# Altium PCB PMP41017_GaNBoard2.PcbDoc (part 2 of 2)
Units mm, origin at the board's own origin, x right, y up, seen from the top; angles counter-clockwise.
Board outline 21.1 x 35.1 mm, 4 copper layers (Top Layer, Layer 1, Layer 2, Bottom Layer), stack 1.926 mm thick; 28 components, 38 nets, 164 pads, 603 vias.
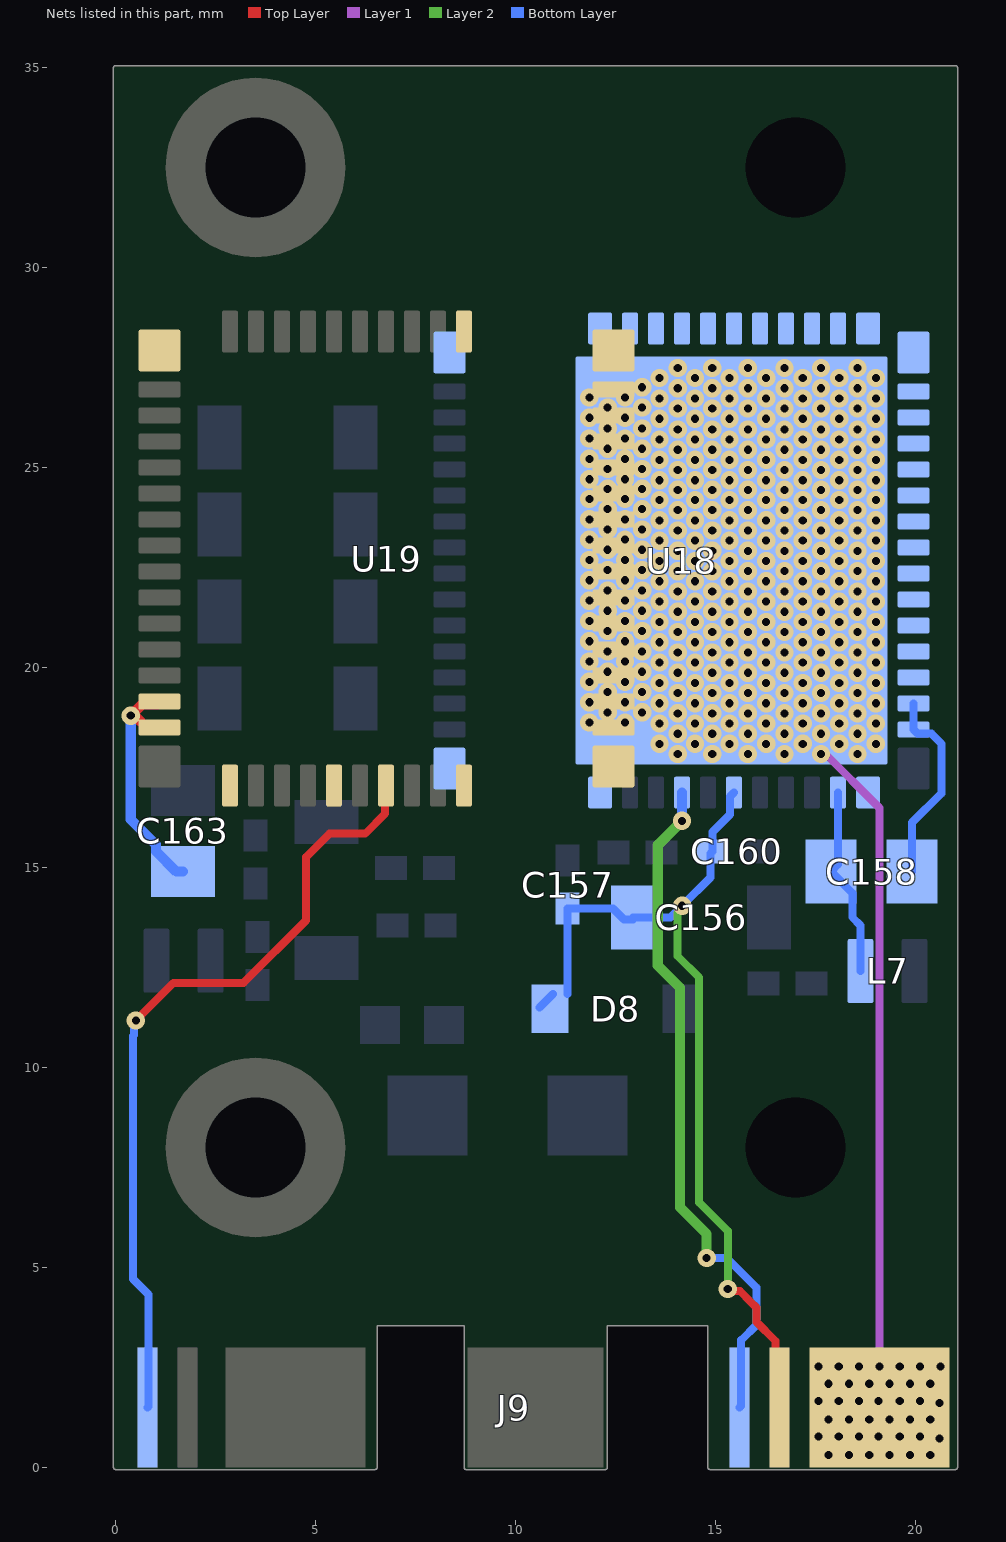
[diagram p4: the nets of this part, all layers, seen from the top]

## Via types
v1: diameter 0.457, hole 0.203, Top Layer to Bottom Layer, tented both sides, 603 vias

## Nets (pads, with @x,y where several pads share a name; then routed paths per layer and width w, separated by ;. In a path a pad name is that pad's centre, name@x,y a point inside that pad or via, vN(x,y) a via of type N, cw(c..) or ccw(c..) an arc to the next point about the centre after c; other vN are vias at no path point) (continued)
SW: C156.2 C157.2 C158.2 C160.1 D8.2 J9.8 J9.SW L7.1 U18.18 U18.19 U18.20 U18.21 U18.22 U18.23 U18.24 U18.25 U18.26 U18.27 U18.29 U18.30 U18.31 U18.32 U18.33 U18.34 U18.35 U18.36 U18.37 U18.38 U18.39 U18.40 U18.44 U18.45 U18.49 U18.55 U19.2 U19.3 U19.4 U19.5 U19.6 U19.7 U19.8 U19.9 U19.10 U19.11 U19.12 U19.13 U19.14 U19.15 | length 44.7
  Top Layer w0.2: v1(15.306,4.464) 15.354,4.417 15.606,4.417 15.877,4.146 16.023,4 16.023,3.641 16.495,3.169 16.495,1.605 J9.8@16.6,1.5
  Layer 1 w0.2: v1@17.694,17.894 19.1,16.488 J9.SW@19.1,1.5
  Layer 2 w0.2: v1(14.167,14.046) 14.167,13.976 14.056,13.865 14.056,12.784 14.592,12.248 14.592,6.628 15.306,5.914 v1(15.306,4.464)
  Bottom Layer w0.2: D8.2@10.601,11.5 D8.2@10.938,11.837 ; D8.2@11.3,11.837 C157.2@11.3,13.973 12.437,13.973 12.71,13.7 C156.2@12.94,13.7 ; C156.2@12.94,13.754 13.873,13.754 14.165,14.046 14.873,14.754 14.873,15.349 C160.1@14.929,15.405 14.927,15.407 14.927,15.888 15.365,16.326 15.365,16.775 U18.49@15.465,16.875 ; U18.45@18.065,16.875 18.065,15.081 C158.2@17.884,14.9 18.419,14.365 18.419,13.758 18.625,13.552 L7.1@18.625,12.411
  other v1: 17.828,0.315 18.336,0.315 18.844,0.315 19.352,0.315 19.86,0.315 20.368,0.315 20.597,0.722 17.574,0.772 18.082,0.772 18.59,0.772 19.073,0.772 19.606,0.772 20.114,0.772 17.828,1.204 18.336,1.204 18.844,1.204 19.352,1.204 19.86,1.204 20.368,1.204 20.597,1.611 17.574,1.661 18.082,1.661 18.59,1.661 19.073,1.661 19.606,1.661 20.114,1.661 17.828,2.093 18.336,2.093 18.844,2.093 19.352,2.093 19.86,2.093 20.368,2.093 17.574,2.525 18.082,2.525 18.59,2.525 19.098,2.525 19.606,2.525 20.114,2.525 20.622,2.525 14.056,17.837 14.919,17.837 15.808,17.837 16.723,17.837 17.637,17.837 18.552,17.837 13.599,18.091 14.488,18.091 15.351,18.091 16.266,18.091 17.18,18.091 18.094,18.091 19.009,18.091 14.056,18.345 14.919,18.345 15.808,18.345 16.723,18.345 17.637,18.345 18.552,18.345 13.599,18.599 14.488,18.599 15.351,18.599 16.266,18.599 17.18,18.599 18.094,18.599 19.009,18.599 11.846,18.625 12.735,18.625 14.056,18.853 14.919,18.853 15.808,18.853 16.723,18.853 17.637,18.853 18.552,18.853 12.303,18.879 13.167,18.879 13.599,19.107 14.488,19.107 15.351,19.107 16.266,19.107 17.18,19.107 18.094,19.107 19.009,19.107 11.846,19.133 12.735,19.133 14.056,19.361 14.919,19.361 15.808,19.361 16.723,19.361 17.637,19.361 18.552,19.361 12.303,19.387 13.167,19.387 13.599,19.615 14.488,19.615 15.351,19.615 16.266,19.615 17.18,19.615 18.094,19.615 19.009,19.615 11.846,19.641 12.735,19.641 14.056,19.869 14.919,19.869 15.808,19.869 16.723,19.869 17.637,19.869 18.552,19.869 12.303,19.895 13.167,19.895 13.599,20.123 14.488,20.123 15.351,20.123 16.266,20.123 17.18,20.123 18.094,20.123 19.009,20.123 11.846,20.149 12.735,20.149 14.056,20.377 14.919,20.377 15.808,20.377 16.723,20.377 17.637,20.377 18.552,20.377 12.303,20.403 13.167,20.403 13.599,20.631 14.488,20.631 15.351,20.631 16.266,20.631 17.18,20.631 18.094,20.631 19.009,20.631 11.846,20.657 12.735,20.657 14.056,20.885 14.919,20.885 15.808,20.885 16.723,20.885 17.637,20.885 18.552,20.885 12.303,20.911 13.167,20.911 13.599,21.139 14.488,21.139 15.351,21.139 16.266,21.139 17.18,21.139 18.094,21.139 19.009,21.139 11.846,21.165 12.735,21.165 14.056,21.393 14.919,21.393 15.808,21.393 16.723,21.393 17.637,21.393 18.552,21.393 12.303,21.419 13.167,21.419 13.599,21.647 14.488,21.647 15.351,21.647 16.266,21.647 17.18,21.647 18.094,21.647 19.009,21.647 11.846,21.673 12.735,21.673 14.056,21.901 14.919,21.901 15.808,21.901 16.723,21.901 17.637,21.901 18.552,21.901 12.303,21.927 13.167,21.927 13.599,22.155 14.488,22.155 15.351,22.155 16.266,22.155 17.18,22.155 18.094,22.155 19.009,22.155 11.846,22.181 12.735,22.181 14.056,22.409 14.919,22.409 15.808,22.409 16.723,22.409 17.637,22.409 18.552,22.409 12.303,22.435 13.167,22.435 13.599,22.663 14.488,22.663 15.351,22.663 16.266,22.663 17.18,22.663 18.094,22.663 19.009,22.663 11.846,22.689 12.735,22.689 14.056,22.917 14.919,22.917 15.808,22.917 16.723,22.917 17.637,22.917 18.552,22.917 12.303,22.943 13.167,22.943 13.599,23.171 14.488,23.171 15.351,23.171 16.266,23.171 17.18,23.171 18.094,23.171 19.009,23.171 11.846,23.197 12.735,23.197 14.056,23.425 14.919,23.425 15.808,23.425 16.723,23.425 17.637,23.425 18.552,23.425 12.303,23.451 13.167,23.451 13.599,23.679 14.488,23.679 15.351,23.679 16.266,23.679 17.18,23.679 18.094,23.679 19.009,23.679 11.846,23.705 12.735,23.705 14.056,23.933 14.919,23.933 15.808,23.933 16.723,23.933 17.637,23.933 18.552,23.933 12.303,23.959 13.167,23.959 13.599,24.187 14.488,24.187 15.351,24.187 16.266,24.187 17.18,24.187 18.094,24.187 19.009,24.187 11.846,24.213 12.735,24.213 14.056,24.441 14.919,24.441 15.808,24.441 16.723,24.441 17.637,24.441 18.552,24.441 12.303,24.467 13.167,24.467 13.599,24.683 14.488,24.683 15.351,24.683 16.266,24.683 17.18,24.683 18.094,24.683 19.009,24.683 11.846,24.708 12.735,24.708 14.056,24.937 14.919,24.937 15.808,24.937 16.723,24.937 17.637,24.937 18.552,24.937 12.303,24.962 13.167,24.962 13.599,25.191 14.488,25.191 15.351,25.191 16.266,25.191 17.18,25.191 18.094,25.191 19.009,25.191 11.846,25.216 12.735,25.216 14.056,25.445 14.919,25.445 15.808,25.445 16.723,25.445 17.637,25.445 18.552,25.445 12.303,25.47 13.167,25.47 13.599,25.699 14.488,25.699 15.351,25.699 16.266,25.699 17.18,25.699 18.094,25.699 19.009,25.699 11.846,25.724 12.735,25.724 14.056,25.953 14.919,25.953 15.808,25.953 16.723,25.953 17.637,25.953 18.552,25.953 12.303,25.978 13.167,25.978 13.599,26.219 14.488,26.219 15.351,26.219 16.266,26.219 17.18,26.219 18.094,26.219 19.009,26.219 11.846,26.245 12.735,26.245 14.056,26.473 14.919,26.473 15.808,26.473 16.723,26.473 17.637,26.473 18.552,26.473 12.303,26.499 13.167,26.499 13.599,26.727 14.488,26.727 15.351,26.727 16.266,26.727 17.18,26.727 18.094,26.727 19.009,26.727 11.846,26.753 12.735,26.753 14.056,26.981 14.919,26.981 15.808,26.981 16.723,26.981 17.637,26.981 18.552,26.981 13.167,27.007 13.599,27.235 14.488,27.235 15.351,27.235 16.266,27.235 17.18,27.235 18.094,27.235 19.009,27.235 14.056,27.489 14.919,27.489 15.808,27.489 16.723,27.489 17.637,27.489 18.552,27.489
TEMP_H_1: J9.5 U18.51 | length 17.1
  Layer 2 w0.254: v1(14.165,16.167) 13.555,15.557 13.555,12.552 14.111,11.997 14.111,6.506 14.778,5.838 v1(14.778,5.239)
  Bottom Layer w0.2: v1(14.778,5.239) 15.28,5.239 16.023,4.496 16.023,3.563 15.643,3.183 15.643,1.543 J9.5@15.6,1.5
  Bottom Layer w0.254: v1(14.165,16.167) U18.51@14.165,16.875
TEMP_L_1: J9.1 U19.49 | length 19.9
  Top Layer w0.2: v1(0.508,11.176) 1.45,12.118 3.202,12.118 4.759,13.675 4.759,15.257 5.348,15.845 6.242,15.845 6.743,16.347 6.743,17.033 U19.49@6.76,17.05
  Bottom Layer w0.2: v1(0.508,11.176) 0.459,11.127 0.459,10.811 0.436,10.788 0.436,4.717 0.828,4.325 0.828,1.528 J9.1@0.8,1.5
U1NC1_1: U18.1
U1NC16_1: U18.16
U1NC17_1: U18.17
U1NC28_1: U18.28
U1NC54_1: U18.54
U2NC1_1: U19.1
U2NC16_1: U19.16
U2NC17_1: U19.17
U2NC27_1: U19.27
U2NC43_1: U19.43
U2NC52_1: U19.52
U2NC57_1: U19.47
VNEG_H_1: C158.1 U18.41 U18.42 | length 5
  Bottom Layer w0.2: C158.1@19.916,14.9 19.916,16.122 20.65,16.856 20.65,18.094 20.394,18.35 20.05,18.35 U18.42@19.95,18.45 U18.41@19.95,19.1
VNEG_L_1: C163.1 U19.40 U19.41 | length 6.1
  Top Layer w0.254: U19.41@0.938,18.5 0.775,18.5 0.518,18.757 0.42,18.757 v1(0.381,18.796) 0.666,19.081 1.031,19.081 U19.40@1.1,19.15
  Bottom Layer w0.254: v1(0.381,18.796) 0.381,16.202 1.013,15.57 1.013,15.405 1.521,14.897 C163.1@1.686,14.897

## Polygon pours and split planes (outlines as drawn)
SW on Bottom Layer "BOTTOM_LAYER_SW_P021" (solid, remove dead copper, pour order 21): 12.115,28.956 19.383,28.956 20.394,27.945 20.394,17.237 19.782,16.625 11.43,16.675 11.43,28.271
HVBUS on Bottom Layer "BOTTOM_LAYER_HVBUS_P017" (solid, remove dead copper, pour order 17): 5.365,26.7 5.778,27.113 9.052,27.113 9.052,18.225 5.263,18.225
PGND on Bottom Layer "BOTTOM_LAYER_PGND_P016" (solid, remove dead copper, pour order 16): 0,16.135 3.83,16.135 3.925,16.23 3.925,27.252 8.881,32.208 8.881,35.052 0.381,35.052 0,34.671
SW on Top Layer "Top Layer-SW" (solid, remove dead copper, pour order 36): 17.353,0.003 20.842,0.003 20.858,0.02 20.858,3.256 20.148,3.966 20.148,29.949 11.43,29.949 11.43,9.109 17.353,3.185
PGND on Top Layer "TOP_LAYER_PGND_P029" (solid, remove dead copper, pour order 29): 1.195,9.022 1.195,4.744 2.422,3.517 2.422,0.142 6.497,0.142 6.497,3.555 6.82,3.878 6.82,13.101 5.274,13.101
PGND on Top Layer "TOP_LAYER_PGND_P028" (solid, remove dead copper, pour order 28): 0.19,9.42 5.013,14.243 5.013,19.46 5.013,27.711 8.881,31.578 8.881,34.29 8.171,35 1.159,35 0.191,34.032
HVBUS on Top Layer "TOP_LAYER_HVBUS_P019" (solid, remove dead copper, pour order 19): 7.959,26.473 6.495,26.473 6.495,18.853 7.959,18.853
PGND on Top Layer "TOP_LAYER_PGND_P018" (solid, remove dead copper, pour order 18): 4.16,17.052 4.16,17.863 4.16,27.144 4.587,27.571 9.052,27.571 9.052,34.658 8.71,35 0.837,35 0.381,34.544 0.381,17.052
PGND on Layer 1 "LAYER_1_PGND_P032" (solid, remove dead copper, pour order 32): 4.16,17.052 4.16,17.863 4.16,27.144 4.587,27.571 9.052,27.571 9.052,34.658 8.71,35 0.837,35 0.381,34.544 0.381,17.052
PGND on Layer 1 "LAYER_1_PGND_P026" (solid, remove dead copper, pour order 26): 2.434,18.288 2.763,18.288 3.5,17.55 3.5,13.113 6.82,13.113 6.82,16.351 5.013,18.157 5.013,19.863 2.434,19.863
SW on Layer 1 "LAYER_1_SW_P031" (solid, remove dead copper, pour order 31): 14.919,5.911 16.176,4.655 16.176,0.017 21,0.082 21,3.555 20.597,3.958 20.597,34.29 12.561,34.29 11.592,33.321 11.592,17.682 14.919,14.354
PGND on Layer 1 "LAYER_1_PGND_P027" (solid, remove dead copper, pour order 27): 3.596,15.33 5.662,13.265 5.813,13.113 6.82,13.113 6.82,3.878 6.497,3.555 6.497,0.142 0.191,0.142 0.191,34.032 1.159,35 8.171,35 8.881,34.29 8.881,31.578 5.013,27.711 5.013,19.46 3.596,19.46
HVBUS on Layer 1 "LAYER_1_HVBUS_P023" (solid, remove dead copper, pour order 23): 5.68,26.7 10.571,26.7 10.83,26.441 10.83,17.57 12.6,15.8 12.6,0 8.505,0 8.505,16.005 5.68,18.829
PGND on Layer 2 "LAYER_2_PGND_P033" (solid, remove dead copper, pour order 33): 4.16,17.052 4.16,17.863 4.16,27.144 4.587,27.571 9.052,27.571 9.052,34.658 8.71,35 0.837,35 0.381,34.544 0.381,17.052
SW on Layer 2 "LAYER_2_SW_P030" (solid, remove dead copper, pour order 30): 14.919,0 14.919,14.354 11.592,17.682 11.592,33.321 12.561,34.29 20.597,34.29 20.597,3.958 21,3.555 21,0.082
PGND on Layer 2 "LAYER_2_PGND_P025" (solid, remove dead copper, pour order 25): 2.434,18.288 3.052,18.288 3.494,17.846 3.494,12.178 6.82,12.178 6.82,16.351 5.013,18.157 5.013,19.863 2.434,19.863
HVBUS on Layer 2 "LAYER_2_HVBUS_P022" (solid, remove dead copper, pour order 22): 8.505,0 8.505,15.776 5.68,18.601 5.68,26.7 10.571,26.7 10.83,26.441 10.83,17.57 12.6,15.8 12.6,0
PGND on Layer 2 "LAYER_2_PGND_P024" (solid, remove dead copper, pour order 24): 3.596,15.33 5.662,13.265 5.813,13.113 6.82,13.113 6.82,3.878 6.497,3.555 6.497,0.142 0.191,0.142 0.191,34.032 1.159,35 8.171,35 8.881,34.29 8.881,31.578 5.013,27.711 5.013,19.46 3.596,19.46

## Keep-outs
Keep-Out Layer:
  text ".Layer_Name" at -20.343,-59.464 h1.52

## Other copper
Top Layer:
  pour cut-out: 15,8 cw(c17,8) 19,8 cw(c17,8)
  text ".Layer_Name" at -20.343,-59.464 h1.52
Layer 1:
  pour cut-out: 5.821,13.721 ccw(c6.222,13.717) 6.622,13.714 6.626,14.168 ccw(c6.226,14.169) 5.825,14.175
Layer 2:
  pour cut-out: 6.818,13.139 6.117,13.139 3.641,15.615 3.641,17.958 3.338,17.958 3.338,15.447 5.927,12.858 6.818,12.858
Bottom Layer:
  text ".Layer_Name" at -20.343,-59.464 h1.52

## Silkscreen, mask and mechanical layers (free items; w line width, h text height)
Top Overlay:
  lines w0.1: 0.039,5.549 0.039,35.049 21,35.049 21,5.549 0.039,5.549
  text "'.PRJ_Number'.PCB_Rev" at 116.739,-34.38 h2.75
  text ".Layer_Name" at -20.343,-59.464 h1.52
Bottom Overlay:
  circle w0.1: c3.5,8 r2.4
  circle w0.1: c3.5,32.5 r2.4
  circle w0.1: c17,32.5 r2.4
  circle w0.1: c17,8 r2.4
  text ".Layer_Name" at -20.343,-59.464 h1.52
Top Paste:
  rectangle: 14.5,20.227 16.7,22.727
  rectangle: 17.215,20.227 19.415,22.727
  rectangle: 14.5,23.229 16.7,25.729
  rectangle: 17.215,23.229 19.415,25.729
  region: 19.415,19.724 17.215,19.724 17.215,17.224 19.415,17.224
  rectangle: 14.5,17.224 16.7,19.724
  rectangle: 17.215,26.231 19.415,28.731
  rectangle: 14.5,26.231 16.7,28.731
  text ".Layer_Name" at -20.343,-59.464 h1.52
Bottom Paste:
  text ".Layer_Name" at -20.343,-59.464 h1.52
Top Solder:
  rectangle: 13.888,16.994 19.888,28.994
  text ".Layer_Name" at -20.343,-59.464 h1.52
  text ".Layer_Name" at -20.343,-59.464 h1.52
Bottom Solder:
  text ".Layer_Name" at -20.343,-59.464 h1.52
Drill Guide:
  text ".Layer_Name" at -20.343,-59.464 h1.52
M1 Board Outline:
  lines w0.1: 21,0.165 21,0 ; 21,0 14.859,0 14.859,3.6 12.246,3.6 12.246,0 8.763,0 8.763,3.6 6.491,3.6 6.491,0 0,0 0,35 21,35 21,0
  text ".Layer_Name" at -20.343,-59.464 h1.52
M2 Board Dimensions:
  rectangle: -34.999,-44.643 -31.824,-41.468
  rectangle: -31.824,-47.818 -22.299,-44.643
  lines w0.178: -34.999,-44.643 -9.599,-44.643 ; -31.824,-47.818 -31.824,-41.468 ; -28.649,-47.818 -28.649,-41.468 ; -22.299,-47.818 -22.299,-41.468 ; -15.949,-47.818 -15.949,-41.468 ; -34.999,-47.818 -9.599,-47.818 -9.599,-41.468 -34.999,-41.468 -34.999,-47.818
  text ".Layer_Name" at -20.343,-59.464 h1.52
M3 3D STEP Top:
  text ".Layer_Name" at -20.343,-59.464 h1.52
M4 3D STEP Bottom:
  text ".Layer_Name" at -20.343,-59.464 h1.52
M5 Assembly Top:
  lines w0.254: -42.416,-61.285 125.224,-61.285 ; -42.416,-56.12 125.275,-56.12 ; -42.416,-50.955 -42.416,-66.449 59.311,-66.449 125.275,-66.449 125.275,-50.955 -42.403,-50.955 -42.403,-66.449 -2.386,-66.449 ; 20.195,-66.449 20.195,-50.955 ; 52.377,-56.12 52.377,-50.955 ; 73.713,-56.12 73.713,-50.955 ; 89.512,-66.614 89.512,-61.463
  text "COMPONENTS MARKED 'DNP' SHOULD NOT BE POPULATED." at -5.7,-45.748 h1.52
  text "ASSEMBLY VARIANT:" at -5.713,-48.682 h1.52
  text ".VariantName" at 20.601,-48.682 h1.52
  text "PCB VIEWED FROM TOP SIDE" at -40.803,-54.312 h1.52
  text "BOARD #:" at 22.1,-54.312 h1.52
  text ".PRJ_Number" at 35.956,-54.312 h1.52
  text "REV:" at 57.406,-54.312 h1.52
  text ".PCB_Rev" at 64.81,-54.312 h1.52
  text "SVN REV:" at 78.691,-54.312 h1.52
  text ".VersionControl_RevNumber" at 91.544,-54.312 h1.52
  text "TID #:" at 22.1,-59.477 h1.52
  text ".TID" at 35.956,-59.477 h1.52
  text "PLOT NAME =" at -40.803,-64.693 h1.52
  text ".plot_File_Name" at -20.343,-64.693 h1.52
  text "GENERATED    :" at 22.151,-64.693 h1.52
  text ".Print_Date" at 44.236,-64.693 h1.52
  text ".Print_Time" at 62.753,-64.693 h1.52
  text "TEXAS INSTRUMENTS" at 94.871,-64.693 h1.52
M6 Assembly Bottom:
  lines w0.254: -42.429,-56.133 125.262,-56.133 ; -42.378,-61.297 125.262,-61.297 ; -6.665,-66.627 -6.665,-61.475 ; 9.133,-56.133 9.133,-50.968 ; 30.469,-56.133 30.469,-50.968 ; 62.651,-66.462 62.651,-50.968 ; 85.232,-66.462 125.249,-66.462 125.249,-50.968 -42.429,-50.968 -42.429,-66.462 23.535,-66.462 125.262,-66.462 125.262,-50.968
  text "COMPONENTS MARKED 'DNP' SHOULD NOT BE POPULATED." at 119.992,-45.736 h1.52
  text ".VariantName" at 93.474,-48.682 h1.52
  text "ASSEMBLY VARIANT:" at 119.865,-48.682 h1.52
  text ".VersionControl_RevNumber" at -8.697,-54.325 h1.52
  text "SVN REV:" at 4.155,-54.325 h1.52
  text ".PCB_Rev" at 18.036,-54.325 h1.52
  text "REV:" at 25.44,-54.325 h1.52
  text ".PRJ_Number" at 46.89,-54.325 h1.52
  text "BOARD #:" at 60.746,-54.325 h1.52
  text "PCB VIEWED FROM BOTTOM SIDE" at 123.649,-54.325 h1.52
  text ".TID" at 46.89,-59.49 h1.52
  text "TID #:" at 60.746,-59.49 h1.52
  text "TEXAS INSTRUMENTS" at -12.025,-64.705 h1.52
  text ".Print_Time" at 20.093,-64.705 h1.52
  text ".Print_Date" at 38.61,-64.705 h1.52
  text "GENERATED    :" at 60.695,-64.705 h1.52
  text ".plot_File_Name" at 103.19,-64.705 h1.52
  text "PLOT NAME =" at 123.649,-64.705 h1.52
M9 Title Sheet:
  drawing of 57 lines, arcs and shapes, not listed
  text "1" at -16.207,166.469 h1.78
  text "2" at 47.183,166.469 h1.78
  text "3" at 110.412,166.469 h1.78
  text "4" at 174.081,166.469 h1.78
  text "5" at 237.556,166.469 h1.78
  text "6" at 301.183,166.469 h1.78
  text "A" at -45.578,137.436 h1.78
  text "A" at 330.342,137.436 h1.78
  text "B" at -45.578,76.984 h1.78
  text "B" at 330.342,76.984 h1.78
  text "C" at -45.578,16.659 h1.78
  text "C" at 330.342,16.659 h1.78
  text "PROJECT TITLE:" at 253.126,-30.61 h1.14
  text ".PRJ_Title" at 254.396,-33.996 h1.78
  text "DESIGNED FOR:" at 253.126,-38.255 h1.14
  text ".PRJ_Customer" at 254.396,-41.811 h1.78
  text "D" at -45.578,-43.539 h1.78
  text "D" at 330.342,-43.539 h1.78
  text "FILE NAME:" at 253.126,-45.875 h1.14
  text ".PCB_File_Name_No_Path" at 254.396,-48.923 h1.78
  text "Texas Instruments (TI) and/or its licensors do not warrant the accuracy or completeness of this specification" at 126.9,-53.034 h1.14
  text "ENGINEER:" at 253.126,-53.241 h1.14
  text "LAYOUT BY:" at 291.353,-53.241 h1.14
  text "or any information contained therein. TI and/or its licensors do not warrant that this design will meet" at 125.758,-55.896 h1.14
  text ".PRJ_Engineer" at 254.396,-57.178 h1.78
  text ".PCB_Layout" at 292.635,-57.178 h1.78
  text "the specifications, will be suitable for your application or fit for any particular purpose, or will operate in" at 125.758,-58.757 h1.14
  text ".Layer_Name" at -20.343,-59.464 h1.52
  text "ALTIUM DESIGNER VERSION:" at 291.353,-61.115 h1.14
  text "an implementation. TI and/or its licensors do not warrant that the design is production worthy. You should" at 125.758,-61.619 h1.14
  text "completely validate and test your design implementation to confirm the system functionality for your application." at 126.9,-64.481 h1.14
  text ".print_Scale" at 254.396,-64.502 h1.78
  text ".Application_BuildNumber" at 292.635,-64.502 h1.78
  text "1" at -16.207,-69.751 h1.78
  text "2" at 47.183,-69.751 h1.78
  text "3" at 110.412,-69.751 h1.78
  text "4" at 174.081,-69.751 h1.78
  text "5" at 237.556,-69.751 h1.78
  text "6" at 301.183,-69.751 h1.78
M10 Fab Notes:
  drawing of 189 lines, arcs and shapes, not listed
  text "DESIGN INFORMATION" at 279.504,123.788 h1.52
  text "MIN. TRACK WIDTH:" at 263.132,120.432 h1.52
  text "8" at 290.977,120.432 h1.52
  text "MIL" at 294.908,120.432 h1.52
  text "7.874" at 286.751,117.342 h1.52
  text "MIN. CLEARANCE:" at 263.132,117.28 h1.52
  text "MIL" at 294.908,117.28 h1.52
  text "MIN. VIA PAD SIZE:" at 263.132,114.127 h1.52
  text "24" at 290.215,114.127 h1.52
  text "MIL" at 294.908,114.127 h1.52
  text "0.05mm (2MIL)" at 280.785,110.827 h1.52
  text "MINIMUM ANNULAR RING" at 254.77,110.618 h1.52
  text "EXTERNAL" at 298.769,110.618 h1.52
  text "PER" at 259.85,107.821 h1.52
  text "IPC-D-275 CLASS 2 LEVEL C" at 265.438,107.821 h1.52
  text "MIL, HOLES" at 303.239,105.269 h1.52
  text "+/-" at 293.27,105.051 h1.52
  text "+/-" at 314.962,105.051 h1.52
  text "REGISTRATION TOLERANCES:" at 254.77,105.024 h1.52
  text "METAL" at 285.244,105.024 h1.52
  text "5" at 299.88,105.024 h1.52
  text "3" at 321.038,105.024 h1.52
  text "MIL" at 323.991,105.024 h1.52
  text "HOLE SIZE TOLERANCE (UNLESS OTHERWISE SPECIFIED):" at 254.77,102.527 h1.52
  text "+/-" at 314.962,102.454 h1.52
  text "3" at 321.038,102.427 h1.52
  text "MIL" at 323.991,102.427 h1.52
  text "MATERIAL:" at 252.871,98.931 h1.52
  text "FR-4 High Tg" at 277.926,95.666 h1.52
  text "X" at 274.258,95.463 h1.52
  text "FR-408" at 263.564,95.348 h1.52
  text "OTHER" at 301.359,95.348 h1.52
  text "62 MIL (1.6mm) +/-10%" at 271.695,91.715 h1.52
  text "X" at 268.644,91.653 h1.52
  text "THICKNESS:" at 254.77,91.507 h1.52
  text "OTHER" at 304.331,91.507 h1.52
  text "TOLERANCE:" at 254.77,87.993 h1.52
  text "X" at 276.315,87.993 h1.52
  text "ANSI IPC-6012 TYPE 3 CLASS 2" at 280.837,87.993 h1.52
  text "OTHER +/-" at 280.836,84.331 h1.52
  text "BOW & TWIST:" at 254.77,80.643 h1.52
  text "X" at 276.315,80.643 h1.52
  text "ANSI IPC-6012 TYPE 3 CLASS 2" at 280.837,80.643 h1.52
  text "OTHER +/-" at 280.836,76.917 h1.52
  text "DRILLING:" at 252.871,73.599 h1.52
  text "NC_DRILL FILES" at 297.6,70.928 h1.52
  text "REFERENCE:" at 254.77,70.828 h1.52
  text "X" at 271.464,70.825 h1.52
  text "AS SHOWN" at 275.985,70.828 h1.52
  text "X" at 294.349,70.828 h1.52
  text "OTHER" at 305.169,67.214 h1.52
  text "PTH COPPER THICKNESS:" at 254.762,67.125 h1.52
  text "X" at 283.698,67.125 h1.52
  text "20-30 um" at 286.949,67.125 h1.52
  text "BOARD FINISH:" at 252.871,63.376 h1.52
  text "SILKSCREEN:" at 256.813,60.579 h1.52
  text "X" at 281.141,60.579 h1.52
  text "TOP" at 284.113,60.579 h1.52
  text "X" at 294.095,60.579 h1.52
  text "BOTTOM" at 297.092,60.579 h1.52
  text "SILKSCREEN COLOR:" at 256.813,56.637 h1.52
  text "X" at 281.116,56.637 h1.52
  text "WHITE" at 284.113,56.637 h1.52
  text "OTHER" at 297.092,56.637 h1.52
  text "X" at 284.443,52.993 h1.52
  text "GREEN" at 287.44,52.993 h1.52
  text "OTHER" at 303.137,52.993 h1.52
  text "SOLDER RESIST COLOR:" at 256.813,52.819 h1.52
  text "X" at 284.443,49.075 h1.52
  text "MATTE" at 287.44,49.075 h1.52
  text "SEMI-GLOSS" at 303.126,49.059 h1.52
  text "IMMERSION GOLD (ENIG)" at 279.82,44.687 h1.52
  text "ENEPIG" at 313.794,44.503 h1.52
  text "SURFACE FINISH:" at 252.871,44.478 h1.52
  text "X" at 275.299,44.478 h1.52
  text "IMM. TIN/SILVER OR EQUIV" at 261.241,40.99 h1.52
  text "OTHER" at 297.6,40.89 h1.52
  text "ARRAY/PANEL:" at 252.871,36.944 h1.52
  text "CUT AND TRIM PER M1 BOARD OUTLINE" at 279.82,36.735 h1.52
  text "N.C. ROUTE" at 279.82,33.281 h1.52
  text "X" at 297.295,33.281 h1.52
  text "V. SCORE" at 301.817,33.281 h1.52
  text "CERTIFICATION:" at 252.871,30.001 h1.52
  text "MATERIALS AND WORKMANSHIP FOR ALL PCBS" at 271.286,30.001 h1.52
  text "TO MEET OR EXCEED THE REQUIREMENTS OF:" at 271.286,27.612 h1.52
  text "X" at 262.078,24.345 h1.52
  text "ANSI IPC-A-600F CLASS ->" at 265.33,24.345 h1.52
  text "X" at 307.189,24.345 h1.52
  text "2" at 309.983,24.345 h1.52
  text "1" at 301.982,24.307 h1.52
  text "3" at 318.974,24.307 h1.52
  text "X" at 282.703,20.594 h1.52
  text "RoHS" at 285.954,20.594 h1.52
  text "OTHER" at 302.322,20.594 h1.52
  text "PER ORDER" at 312.407,20.594 h1.52
  text "ALL BOARDS MUST MEET OR EXCEED UL94-V0 REQUIREMENTS." at 253.57,16.687 h1.52
  text "PCB MUST BEAR THE UL94V-0 UL REGISTERED MATERIAL ID NUMBER" at 253.57,13.739 h1.52
  text "ADDITIONAL REQUIREMENTS:" at 252.871,9.435 h1.52
  text "MICROSECTION:" at 254.77,6.714 h1.52
  text "YES" at 277.776,6.714 h1.52
  text "REQUIRED" at 299.658,3.048 h1.52
  text "BARE BOARD ELEC. TEST:" at 254.77,2.976 h1.52
  text "NONE" at 287.936,2.976 h1.52
  text "X" at 296.66,2.976 h1.52
  text "PER ORDER" at 314.694,2.976 h1.52
  text "XX MIL VIAS REQUIRE NON-CONDUCTIVE FILL AND PLANARIZE" at 259.041,-2.23 h1.5
  text "XX MIL VIAS REQUIRE CONDUCTIVE FILL AND PLANARIZE" at 259.244,-4.871 h1.52
  text "OUTER XX MIL TRACES REQUIRE 50 OHM SINGLE-ENDED IMPEDANCE" at 259.219,-9.021 h1.47
  text "LAYER 2 & 3 (INNER LAYERS) XX MIL WIDE, XX MIL SPACE / TRACES REQUIRE 100 OHM DIFFERENTIAL IMPEDANCE" at 259.016,-15.008 h1.52
  text ".Layer_Name" at -20.343,-59.464 h1.52
M11 Gerber Information:
  lines w0.254: -42.416,-61.285 125.224,-61.285 ; -42.416,-56.12 125.275,-56.12 ; -42.416,-50.955 -42.416,-66.449 59.311,-66.449 125.275,-66.449 125.275,-50.955 -42.403,-50.955 -42.403,-66.449 -2.386,-66.449 ; 20.195,-66.449 20.195,-50.955 ; 52.377,-56.12 52.377,-50.955 ; 73.713,-56.12 73.713,-50.955 ; 89.512,-66.614 89.512,-61.463
  text "ALL ARTWORK VIEWED FROM TOP SIDE" at -40.803,-54.312 h1.52
  text "BOARD #:" at 22.1,-54.312 h1.52
  text ".PRJ_Number" at 35.956,-54.312 h1.52
  text "REV:" at 57.406,-54.312 h1.52
  text ".PCB_Rev" at 64.81,-54.312 h1.52
  text "SVN REV:" at 78.691,-54.312 h1.52
  text ".VersionControl_RevNumber" at 91.544,-54.312 h1.52
  text "LAYER NAME =" at -40.803,-59.464 h1.52
  text "TID #:" at 22.1,-59.477 h1.52
  text ".TID" at 35.956,-59.477 h1.52
  text "PLOT NAME =" at -40.803,-64.693 h1.52
  text ".plot_File_Name" at -20.343,-64.693 h1.52
  text "GENERATED    :" at 22.151,-64.693 h1.52
  text ".Print_Date" at 44.236,-64.693 h1.52
  text ".Print_Time" at 62.753,-64.693 h1.52
  text "TEXAS INSTRUMENTS" at 94.871,-64.693 h1.52
M12 Stackup:
  drawing of 297 lines, arcs and shapes, not listed
  text "Layer" at 214.469,162.365 h1.52
  text "Name" at 224.881,162.365 h1.52
  text "Material" at 248.497,162.365 h1.52
  text "Thickness" at 270.335,162.365 h1.52
  text "Constant" at 286.841,162.365 h1.52
  text "Board Layer Stack" at 301.315,162.365 h1.52
  text "Top Overlay" at 224.881,159.317 h1.52
  text "Top Solder" at 224.881,156.269 h1.52
  text "Solder Resist" at 248.497,156.269 h1.52
  text "0.40mil" at 270.335,156.269 h1.52
  text "3.5" at 286.841,156.269 h1.52
  text "1" at 214.469,153.221 h1.52
  text "Top Layer" at 224.881,153.221 h1.52
  text "CF-005" at 248.497,153.221 h1.52
  text "2.76mil" at 270.335,153.221 h1.52
  text "Dielectric 1" at 224.881,150.173 h1.52
  text "PP-006" at 248.497,150.173 h1.52
  text "2.80mil" at 270.335,150.173 h1.52
  text "4.1" at 286.841,150.173 h1.52
  text "2" at 214.469,147.125 h1.52
  text "Layer 1" at 224.881,147.125 h1.52
  text "CF-005" at 248.497,147.125 h1.52
  text "2.76mil" at 270.335,147.125 h1.52
  text "Dielectric1" at 224.881,144.077 h1.52
  text "FR-4 High Tg" at 248.497,144.077 h1.52
  text "59.20mil" at 270.335,144.077 h1.52
  text "4.8" at 286.841,144.077 h1.52
  text "3" at 214.469,141.029 h1.52
  text "Layer 2" at 224.881,141.029 h1.52
  text "CF-005" at 248.497,141.029 h1.52
  text "2.76mil" at 270.335,141.029 h1.52
  text "Dielectric 2" at 224.881,137.981 h1.52
  text "PP-006" at 248.497,137.981 h1.52
  text "2.80mil" at 270.335,137.981 h1.52
  text "4.1" at 286.841,137.981 h1.52
  text "4" at 214.469,134.933 h1.52
  text "Bottom Layer" at 224.881,134.933 h1.52
  text "CF-005" at 248.497,134.933 h1.52
  text "2.76mil" at 270.335,134.933 h1.52
  text "Bottom Solder" at 224.881,131.885 h1.52
  text "Solder Resist" at 248.497,131.885 h1.52
  text "0.40mil" at 270.335,131.885 h1.52
  text "3.5" at 286.841,131.885 h1.52
  text "Bottom Overlay" at 224.881,128.837 h1.52
  text ".Layer_Name" at -20.343,-59.464 h1.52
M13 Component Bodies Top:
  text ".Layer_Name" at -20.343,-59.464 h1.52
M14 Component Bodies Bottom:
  text ".Layer_Name" at -20.343,-59.464 h1.52
M15 Courtyards Top:
  text ".Layer_Name" at -20.343,-59.464 h1.52
M16 Courtyards Bottom:
  text ".Layer_Name" at -20.343,-59.464 h1.52
Drill Drawing:
  lines w0.254: 37.419,8.927 38.12,8.226 38.822,8.927 38.12,9.629 37.419,8.927
  lines w0.305: 36.146,7.278 118.226,7.278 ; 36.146,13.594 118.226,13.594 ; 44.728,4.121 44.728,16.752 ; 53.161,4.121 53.161,16.752 ; 69.329,4.121 69.329,16.752 ; 75.912,4.121 75.912,16.752 ; 85.441,4.121 85.441,16.752 ; 103.839,4.121 103.839,16.752 ; 36.146,4.121 118.226,4.121 118.226,16.752 36.146,16.752 36.146,4.121
  text "Symbol" at 38.041,14.541 h1.83
  text "Quantity" at 45.675,14.541 h1.83
  text "Finished Hole Size" at 54.108,14.541 h1.83
  text "Plated" at 70.277,14.541 h1.83
  text "Hole Type" at 76.859,14.541 h1.83
  text "Drill Layer Pair" at 86.388,14.541 h1.83
  text "Hole Tolerance" at 104.786,14.541 h1.83
  text "4" at 45.675,11.383 h1.52
  text "98.43mil (2.500mm)" at 54.108,11.383 h1.52
  text "NPTH" at 70.277,11.383 h1.52
  text "Round" at 76.859,11.383 h1.52
  text "Top Layer - Bottom Layer" at 86.388,11.383 h1.52
  text "B" at 37.399,11.13 h1.4
  text "603" at 45.675,8.226 h1.52
  text "8.00mil (0.203mm)" at 54.108,8.226 h1.52
  text "PTH" at 70.277,8.226 h1.52
  text "Round" at 76.859,8.226 h1.52
  text "Top Layer - Bottom Layer" at 86.388,8.226 h1.52
  text "607 Total" at 45.675,5.068 h1.52
  text ".Layer_Name" at -20.343,-59.464 h1.52
M17 Embedded Cavity:
  text ".Layer_Name" at -20.343,-59.464 h1.52
M18 Embedded Assembly:
  text ".Layer_Name" at -20.343,-59.464 h1.52
M19 Embedded Keepout:
  circle w1.2: c17,32.5 r3.039
  circle w1.2: c17,8 r3.039
  text ".Layer_Name" at -20.343,-59.464 h1.52

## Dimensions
0.039,5.549 to 0,35 on M2 Board Dimensions
0,35 to 21,35 on M2 Board Dimensions
-34.999,-47.818 to -9.599,-47.818 on M2 Board Dimensions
